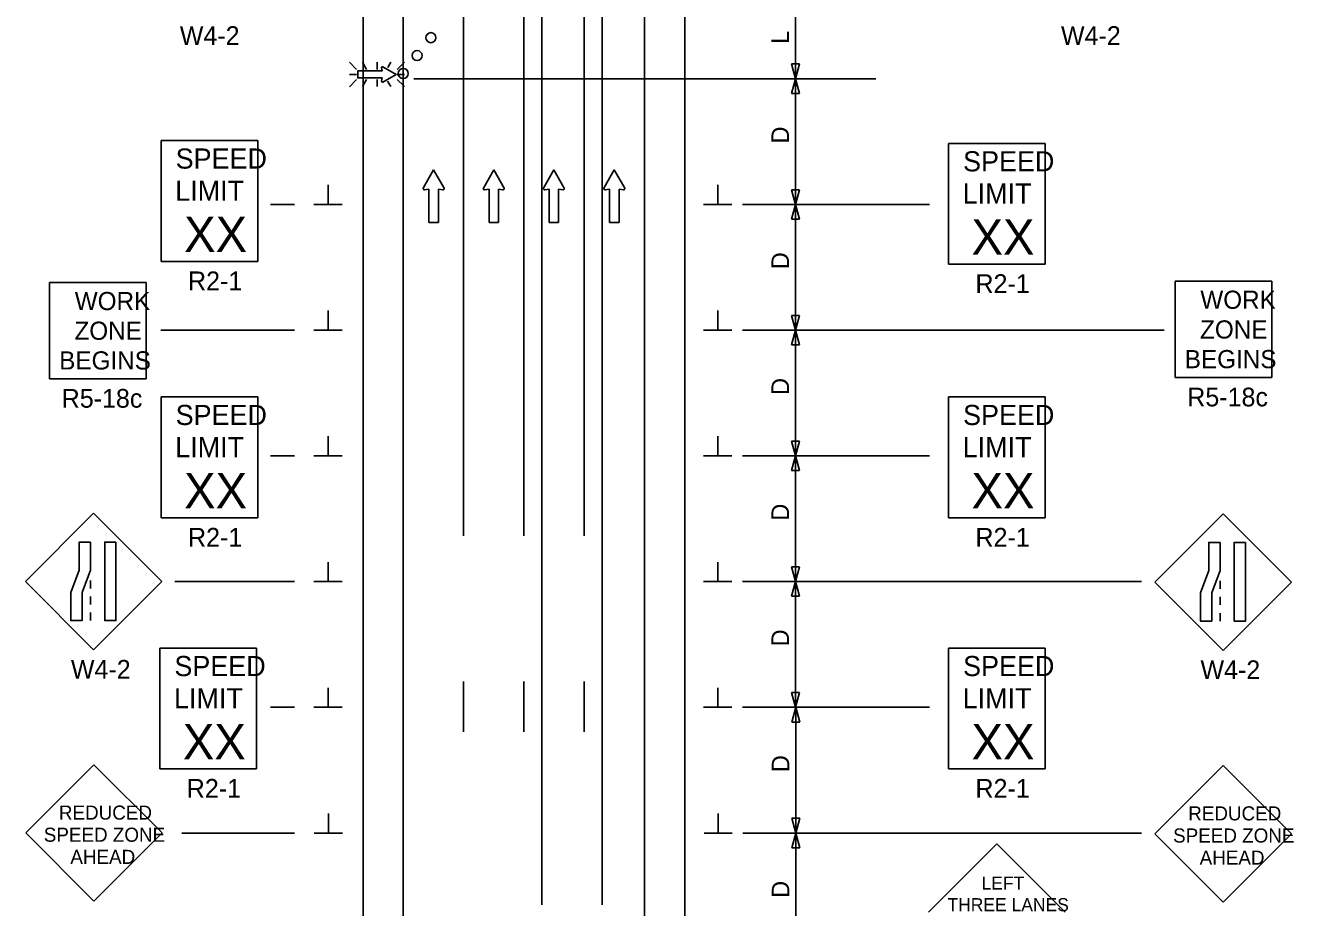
# Model space of a CAD drawing. Extents: x 16383 to 18481, y 5609 to 7023.
# Drawn here: x 16724 to 17229, y 6175 to 6526 of the extents above; entities that cross this region are included whole.
import ezdxf

# ---------------------------------------------------------------- set-up
doc = ezdxf.new("R2010")
doc.units = 0
for name, color, linetype in [('ALI_LEGAL_EX', 7, 'Continuous'), ('MT_SCRATCH_LEVEL_E', 7, 'Continuous'), ('PAVT_EDGE_EX', 7, 'Continuous'), ('TRAFFIC_SIGNS_PR', 7, 'Continuous'), ('TYPICAL_TEXT_DIMEN_PR', 7, 'Continuous')]:
    doc.layers.add(name, color=color, linetype=linetype)

msp = doc.modelspace()

# ---------------------------------------------------------------- linework, layer by layer
at = {"layer": 'ALI_LEGAL_EX'}
for p, q in [((16898.69, 7022.86), (16898.69, 6323.13)), ((16922.69, 7022.86), (16922.69, 6323.13)), ((16946.69, 7022.86), (16946.69, 6323.13)), ((16929.88, 7005.57), (16929.88, 6176.39)), ((16953.88, 7005.57), (16953.88, 6176.39)), ((16953.88, 7005.57), (16953.88, 6176.39))]:
    msp.add_line(p, q, dxfattribs=at)
for points in [[(16898.69, 6470.26), (16898.69, 6445.26)], [(16922.69, 6470.26), (16922.69, 6445.26)], [(16946.69, 6470.26), (16946.69, 6445.26)], [(16898.69, 6370.26), (16898.69, 6345.26)], [(16922.69, 6370.26), (16922.69, 6345.26)], [(16946.69, 6370.26), (16946.69, 6345.26)], [(16898.69, 6265.21), (16898.69, 6245.26)], [(16922.69, 6265.21), (16922.69, 6245.26)], [(16946.69, 6265.21), (16946.69, 6245.26)]]:
    msp.add_lwpolyline(points, dxfattribs=at)
at = {"layer": 'MT_SCRATCH_LEVEL_E'}
for p, q in [((16886.79, 6468.72), (16882.68, 6461.48)), ((16890.94, 6461.48), (16886.79, 6468.72)), ((16910.69, 6468.72), (16906.58, 6461.48)), ((16914.84, 6461.48), (16910.69, 6468.72)), ((16934.6, 6468.72), (16930.49, 6461.48)), ((16938.74, 6461.48), (16934.6, 6468.72)), ((16958.65, 6468.72), (16954.54, 6461.48)), ((16962.8, 6461.48), (16958.65, 6468.72)), ((16883.16, 6460.79), (16884.94, 6461.11)), ((16884.94, 6461.11), (16884.94, 6447.85)), ((16888.68, 6447.85), (16888.68, 6461.11)), ((16888.68, 6461.11), (16890.46, 6460.79)), ((16907.06, 6460.79), (16908.84, 6461.11)), ((16908.84, 6461.11), (16908.84, 6447.85)), ((16912.58, 6447.85), (16912.58, 6461.11)), ((16912.58, 6461.11), (16914.36, 6460.79)), ((16930.97, 6460.79), (16932.74, 6461.11)), ((16932.74, 6461.11), (16932.74, 6447.85)), ((16936.49, 6447.85), (16936.49, 6461.11)), ((16936.49, 6461.11), (16938.26, 6460.79)), ((16955.02, 6460.79), (16956.8, 6461.11)), ((16956.8, 6461.11), (16956.8, 6447.85)), ((16960.54, 6447.85), (16960.54, 6461.11)), ((16960.54, 6461.11), (16962.32, 6460.79)), ((16884.94, 6447.85), (16888.68, 6447.85)), ((16908.84, 6447.85), (16912.58, 6447.85)), ((16932.74, 6447.85), (16936.49, 6447.85)), ((16956.8, 6447.85), (16960.54, 6447.85))]:
    msp.add_line(p, q, dxfattribs=at)
for centre, start, end in [((16883.09, 6461.25), 150.4248, 279.9638), ((16890.53, 6461.25), 260.0362, 29.7731), ((16906.99, 6461.25), 150.4248, 279.9638), ((16914.43, 6461.25), 260.0362, 29.7731), ((16930.89, 6461.25), 150.4248, 279.9638), ((16938.33, 6461.25), 260.0362, 29.7731), ((16954.95, 6461.25), 150.4248, 279.9638), ((16962.39, 6461.25), 260.0362, 29.7731)]:
    msp.add_arc(centre, 0.463, start, end, dxfattribs=at)
at = {"layer": 'PAVT_EDGE_EX'}
for p, q in [((16858.69, 6927.61), (16858.69, 6052.61)), ((16874.69, 6927.61), (16874.69, 6052.61)), ((16970.69, 6927.61), (16970.69, 6052.61)), ((16986.69, 6927.61), (16986.69, 6052.61))]:
    msp.add_line(p, q, dxfattribs=at)
at = {"layer": 'TRAFFIC_SIGNS_PR'}
for p, q in [((16856.17, 6508.7), (16853.35, 6511.52)), ((16858.47, 6511.52), (16860.1, 6508.7)), ((16864.26, 6508.7), (16864.26, 6511.52)), ((16869.73, 6511.52), (16868.52, 6509.43)), ((16875.16, 6511.52), (16872.34, 6508.7)), ((16856.17, 6506.67), (16853.35, 6506.67)), ((16856.17, 6504.64), (16853.35, 6501.81)), ((16860.12, 6504.64), (16858.49, 6501.82)), ((16864.26, 6504.64), (16864.26, 6501.82)), ((16868.44, 6504), (16869.7, 6501.82)), ((16872.34, 6506.67), (16875.16, 6506.67)), ((16875.16, 6501.82), (16872.34, 6504.64)), ((16778.39, 6480.38), (16816.84, 6480.38)), ((16778.39, 6432.32), (16778.39, 6480.38)), ((16816.84, 6432.32), (16816.84, 6480.38)), ((17091.61, 6479.27), (17130.06, 6479.27)), ((17091.61, 6431.21), (17091.61, 6479.27)), ((17130.06, 6431.21), (17130.06, 6479.27)), ((16778.39, 6432.32), (16816.84, 6432.32)), ((17091.61, 6431.21), (17130.06, 6431.21)), ((16734.04, 6385.58), (16734.04, 6423.98)), ((16734.04, 6423.98), (16772.44, 6423.98)), ((16772.44, 6385.58), (16772.44, 6423.98)), ((17181.76, 6386.1), (17181.76, 6424.5)), ((17181.76, 6424.5), (17220.16, 6424.5)), ((17220.16, 6386.1), (17220.16, 6424.5)), ((16734.04, 6385.58), (16772.44, 6385.58)), ((17181.76, 6386.1), (17220.16, 6386.1)), ((16778.39, 6378.4), (16816.84, 6378.4)), ((16778.39, 6330.34), (16778.39, 6378.4)), ((16816.84, 6330.34), (16816.84, 6378.4)), ((17091.61, 6378.4), (17130.06, 6378.4)), ((17091.61, 6330.34), (17091.61, 6378.4)), ((17130.06, 6330.34), (17130.06, 6378.4)), ((16751.54, 6332.13), (16724.39, 6304.97)), ((16778.7, 6304.97), (16751.54, 6332.13)), ((17200.86, 6331.94), (17173.71, 6304.79)), ((17228.02, 6304.79), (17200.86, 6331.94)), ((16778.39, 6330.34), (16816.84, 6330.34)), ((17091.61, 6330.34), (17130.06, 6330.34)), ((16724.39, 6304.97), (16751.54, 6277.82)), ((16750.3, 6305.46), (16750.3, 6302.26)), ((16751.54, 6277.82), (16778.7, 6304.97)), ((17173.71, 6304.79), (17200.86, 6277.64)), ((17199.62, 6305.28), (17199.62, 6302.08)), ((17200.86, 6277.64), (17228.02, 6304.79)), ((16750.3, 6299.06), (16750.3, 6295.86)), ((17199.62, 6298.88), (17199.62, 6295.68)), ((16750.3, 6292.66), (16750.3, 6289.46)), ((17199.62, 6292.48), (17199.62, 6289.28)), ((16777.9, 6278.55), (16816.35, 6278.55)), ((16777.9, 6230.49), (16777.9, 6278.55)), ((16816.35, 6230.49), (16816.35, 6278.55)), ((17091.61, 6278.55), (17130.06, 6278.55)), ((17091.61, 6230.49), (17091.61, 6278.55)), ((17130.06, 6230.49), (17130.06, 6278.55)), ((16751.67, 6232.15), (16724.52, 6205)), ((16778.83, 6205), (16751.67, 6232.15)), ((16777.9, 6230.49), (16816.35, 6230.49)), ((17091.61, 6230.49), (17130.06, 6230.49)), ((17200.87, 6231.85), (17173.72, 6204.7)), ((17228.02, 6204.7), (17200.87, 6231.85)), ((16724.52, 6205), (16751.67, 6177.85)), ((16751.67, 6177.85), (16778.83, 6205)), ((17110.78, 6200.7), (17083.62, 6173.54)), ((17137.93, 6173.54), (17110.78, 6200.7)), ((17173.72, 6204.7), (17200.87, 6177.54)), ((17200.87, 6177.54), (17228.02, 6204.7))]:
    msp.add_line(p, q, dxfattribs=at)
for points in [[(16866.08, 6509.35), (16866.31, 6508.05), (16856.59, 6508.05), (16856.59, 6505.31), (16866.31, 6505.31), (16866.08, 6504.01)], [(16866.58, 6503.65), (16871.89, 6506.67), (16866.58, 6509.71)]]:
    msp.add_lwpolyline(points, dxfattribs=at)
for points in [[(16750.3, 6320.71), (16750.3, 6309.53), (16746.95, 6300.65), (16746.95, 6289.46), (16742.46, 6289.46), (16742.46, 6300.65), (16745.8, 6309.53), (16745.8, 6320.71)], [(16760.43, 6320.71), (16760.43, 6289.46), (16755.94, 6289.46), (16755.94, 6320.71)], [(17199.62, 6320.53), (17199.62, 6309.35), (17196.27, 6300.46), (17196.27, 6289.28), (17191.78, 6289.28), (17191.78, 6300.46), (17195.12, 6309.35), (17195.12, 6320.53)], [(17209.75, 6320.53), (17209.75, 6289.28), (17205.26, 6289.28), (17205.26, 6320.53)]]:
    msp.add_lwpolyline(points, close=True, dxfattribs=at)
for centre in [(16885.7, 6521.29), (16880.2, 6514.16), (16874.7, 6507.03)]:
    msp.add_circle(centre, 2, dxfattribs=at)
for centre, start, end in [((16866.42, 6509.41), 61.4833, 189.9593), ((16866.42, 6503.95), 170.7308, 298.8916)]:
    msp.add_arc(centre, 0.341, start, end, dxfattribs=at)
at = {"layer": 'TYPICAL_TEXT_DIMEN_PR'}
for p, q in [((17030.69, 6504.98), (17030.69, 6535.54)), ((17030.69, 6504.98), (17029.12, 6510.84)), ((17029.12, 6510.84), (17030.69, 6510.84)), ((17030.69, 6510.84), (17032.26, 6510.84)), ((17032.26, 6510.84), (17030.69, 6504.98)), ((16878.96, 6504.98), (17062.74, 6504.98)), ((16907.09, 6504.98), (17061.13, 6504.98)), ((17029.12, 6499.12), (17030.69, 6504.98)), ((17030.69, 6504.98), (17030.69, 6454.98)), ((17030.69, 6504.98), (17032.26, 6499.12)), ((17030.69, 6499.12), (17029.12, 6499.12)), ((17032.26, 6499.12), (17030.69, 6499.12)), ((16844.81, 6454.98), (16844.81, 6462.77)), ((16999.82, 6454.98), (16999.82, 6462.77)), ((17030.69, 6454.98), (17029.12, 6460.84)), ((17029.12, 6460.84), (17030.69, 6460.84)), ((17030.69, 6460.84), (17032.26, 6460.84)), ((17032.26, 6460.84), (17030.69, 6454.98)), ((16831.38, 6454.98), (16821.91, 6454.98)), ((16850.44, 6454.98), (16839.19, 6454.98)), ((17005.44, 6454.98), (16994.19, 6454.98)), ((17052.11, 6454.98), (17009.69, 6454.98)), ((17029.12, 6449.12), (17030.69, 6454.98)), ((17030.69, 6454.98), (17030.69, 6404.98)), ((17030.69, 6454.98), (17032.26, 6449.12)), ((17084, 6454.98), (17052.11, 6454.98)), ((17030.69, 6449.12), (17029.12, 6449.12)), ((17032.26, 6449.12), (17030.69, 6449.12)), ((16844.81, 6404.98), (16844.81, 6412.77)), ((16999.82, 6404.98), (16999.82, 6412.77)), ((17030.69, 6404.98), (17029.12, 6410.84)), ((17029.12, 6410.84), (17030.69, 6410.84)), ((17030.69, 6410.84), (17032.26, 6410.84)), ((17032.26, 6410.84), (17030.69, 6404.98)), ((16831.38, 6404.98), (16778.23, 6404.98)), ((16850.44, 6404.98), (16839.19, 6404.98)), ((17005.44, 6404.98), (16994.19, 6404.98)), ((17053.72, 6404.98), (17009.69, 6404.98)), ((17029.12, 6399.12), (17030.69, 6404.98)), ((17030.69, 6404.98), (17030.69, 6354.98)), ((17030.69, 6404.98), (17032.26, 6399.12)), ((17177.43, 6404.98), (17053.72, 6404.98)), ((17030.69, 6399.12), (17029.12, 6399.12)), ((17032.26, 6399.12), (17030.69, 6399.12)), ((16844.81, 6354.98), (16844.81, 6362.77)), ((16999.82, 6354.98), (16999.82, 6362.77)), ((17030.69, 6354.98), (17029.12, 6360.84)), ((17029.12, 6360.84), (17030.69, 6360.84)), ((17030.69, 6360.84), (17032.26, 6360.84)), ((17032.26, 6360.84), (17030.69, 6354.98)), ((16831.38, 6354.98), (16821.91, 6354.98)), ((16850.44, 6354.98), (16839.19, 6354.98)), ((17005.44, 6354.98), (16994.19, 6354.98)), ((17052.11, 6354.98), (17009.69, 6354.98)), ((17029.12, 6349.12), (17030.69, 6354.98)), ((17030.69, 6354.98), (17030.69, 6304.98)), ((17030.69, 6354.98), (17032.26, 6349.12)), ((17084, 6354.98), (17052.11, 6354.98)), ((17030.69, 6349.12), (17029.12, 6349.12)), ((17032.26, 6349.12), (17030.69, 6349.12)), ((16844.81, 6304.98), (16844.81, 6312.77)), ((16999.82, 6304.98), (16999.82, 6312.77)), ((17030.69, 6304.98), (17029.12, 6310.84)), ((17029.12, 6310.84), (17030.69, 6310.84)), ((17030.69, 6310.84), (17032.26, 6310.84)), ((17032.26, 6310.84), (17030.69, 6304.98)), ((16831.38, 6304.98), (16783.85, 6304.98)), ((16850.44, 6304.98), (16839.19, 6304.98)), ((17005.44, 6304.98), (16994.19, 6304.98)), ((17052.41, 6304.98), (17009.69, 6304.98)), ((17029.12, 6299.12), (17030.69, 6304.98)), ((17030.69, 6304.98), (17030.69, 6254.98)), ((17030.69, 6304.98), (17032.26, 6299.12)), ((17168.36, 6304.98), (17052.41, 6304.98)), ((17030.69, 6299.12), (17029.12, 6299.12)), ((17032.26, 6299.12), (17030.69, 6299.12)), ((16844.81, 6254.98), (16844.81, 6262.77)), ((16999.82, 6254.98), (16999.82, 6262.77)), ((17030.69, 6254.98), (17029.12, 6260.84)), ((17029.12, 6260.84), (17030.69, 6260.84)), ((17030.69, 6260.84), (17032.26, 6260.84)), ((17032.26, 6260.84), (17030.69, 6254.98)), ((16831.38, 6254.98), (16821.91, 6254.98)), ((16850.44, 6254.98), (16839.19, 6254.98)), ((17005.44, 6254.98), (16994.19, 6254.98)), ((17051.97, 6254.98), (17009.69, 6254.98)), ((17029.26, 6249.12), (17030.83, 6254.98)), ((17030.83, 6254.98), (17030.83, 6204.98)), ((17030.83, 6254.98), (17032.4, 6249.12)), ((17084, 6254.98), (17051.97, 6254.98)), ((17030.83, 6249.12), (17029.26, 6249.12)), ((17032.4, 6249.12), (17030.83, 6249.12)), ((16844.95, 6204.98), (16844.95, 6212.77)), ((16999.96, 6204.98), (16999.96, 6212.77)), ((17030.83, 6204.98), (17029.26, 6210.84)), ((17029.26, 6210.84), (17030.83, 6210.84)), ((17030.83, 6210.84), (17032.4, 6210.84)), ((17032.4, 6210.84), (17030.83, 6204.98)), ((16831.38, 6204.98), (16786.62, 6204.98)), ((16850.57, 6204.98), (16839.32, 6204.98)), ((17005.58, 6204.98), (16994.33, 6204.98)), ((17052.54, 6204.98), (17009.83, 6204.98)), ((17029.26, 6199.12), (17030.83, 6204.98)), ((17030.83, 6204.98), (17030.83, 6154.98)), ((17030.83, 6204.98), (17032.4, 6199.12)), ((17168.36, 6204.98), (17052.54, 6204.98)), ((17030.83, 6199.12), (17029.26, 6199.12)), ((17032.4, 6199.12), (17030.83, 6199.12))]:
    msp.add_line(p, q, dxfattribs=at)

# ---------------------------------------------------------------- texts
at = {"layer": 'TRAFFIC_SIGNS_PR'}
for s, height, p in [('W4-2', 7.44, (16785.83, 6518.42)), ('W4-2', 7.44, (17136.32, 6518.42)), ('SPEED', 8.01, (16784.17, 6469.22)), ('SPEED', 8.01, (17097.38, 6468.12)), ('LIMIT', 8.01, (16784.01, 6456.41)), ('LIMIT', 8.01, (17097.22, 6455.31)), ('XX', 14.048, (16787.52, 6436.08)), ('XX', 14.048, (17100.73, 6434.98)), ('R2-1', 7.449, (16789.09, 6420.86)), ('R2-1', 7.449, (17102.3, 6419.76)), ('WORK', 7.217, (16744.04, 6412.95)), ('WORK', 7.217, (17191.76, 6413.47)), ('ZONE', 7.217, (16743.92, 6401.14)), ('ZONE', 7.217, (17191.64, 6401.65)), ('BEGINS', 7.217, (17185.57, 6389.85)), ('BEGINS', 7.217, (16737.85, 6389.33)), ('R5-18c', 7.44, (16738.85, 6374.14)), ('R5-18c', 7.44, (17186.57, 6374.66)), ('SPEED', 8.01, (16784.17, 6367.24)), ('SPEED', 8.01, (17097.38, 6367.24)), ('LIMIT', 8.01, (16784.01, 6354.43)), ('LIMIT', 8.01, (17097.22, 6354.43)), ('XX', 14.048, (16787.52, 6334.1)), ('XX', 14.048, (17100.73, 6334.1)), ('R2-1', 7.449, (16789.09, 6318.88)), ('R2-1', 7.449, (17102.3, 6318.88)), ('W4-2', 7.44, (16742.5, 6266.38)), ('SPEED', 8.01, (16783.67, 6267.39)), ('SPEED', 8.01, (17097.38, 6267.39)), ('W4-2', 7.44, (17191.82, 6266.2)), ('LIMIT', 8.01, (16783.51, 6254.58)), ('LIMIT', 8.01, (17097.22, 6254.58)), ('XX', 14.048, (16787.02, 6234.25)), ('XX', 14.048, (17100.73, 6234.25)), ('R2-1', 7.449, (16788.59, 6219.03)), ('R2-1', 7.449, (17102.3, 6219.03)), ('REDUCED', 5.6, (16737.73, 6210.31)), ('REDUCED', 5.6, (17186.93, 6210)), ('SPEED ZONE', 5.6, (16731.72, 6201.51)), ('SPEED ZONE', 5.6, (17180.92, 6201.2)), ('AHEAD', 5.6, (16742.28, 6192.71)), ('AHEAD', 5.6, (17191.48, 6192.4)), ('LEFT', 5.2, (17104.72, 6182.48)), ('THREE LANES', 5.2, (17091.17, 6173.88))]:
    msp.add_text(s, height=height, dxfattribs=at).set_placement(p)
at = {"layer": 'TYPICAL_TEXT_DIMEN_PR'}
for s, p in [('L', (17028.14, 6518.84)), ('D', (17028.14, 6479.2)), ('D', (17028.14, 6429.2)), ('D', (17028.14, 6379.2)), ('D', (17028.14, 6329.2)), ('D', (17028.14, 6279.2)), ('D', (17028.27, 6229.2)), ('D', (17028.27, 6179.2))]:
    msp.add_text(s, height=7, rotation=90, dxfattribs=at).set_placement(p)

doc.saveas('drawing.dxf')
